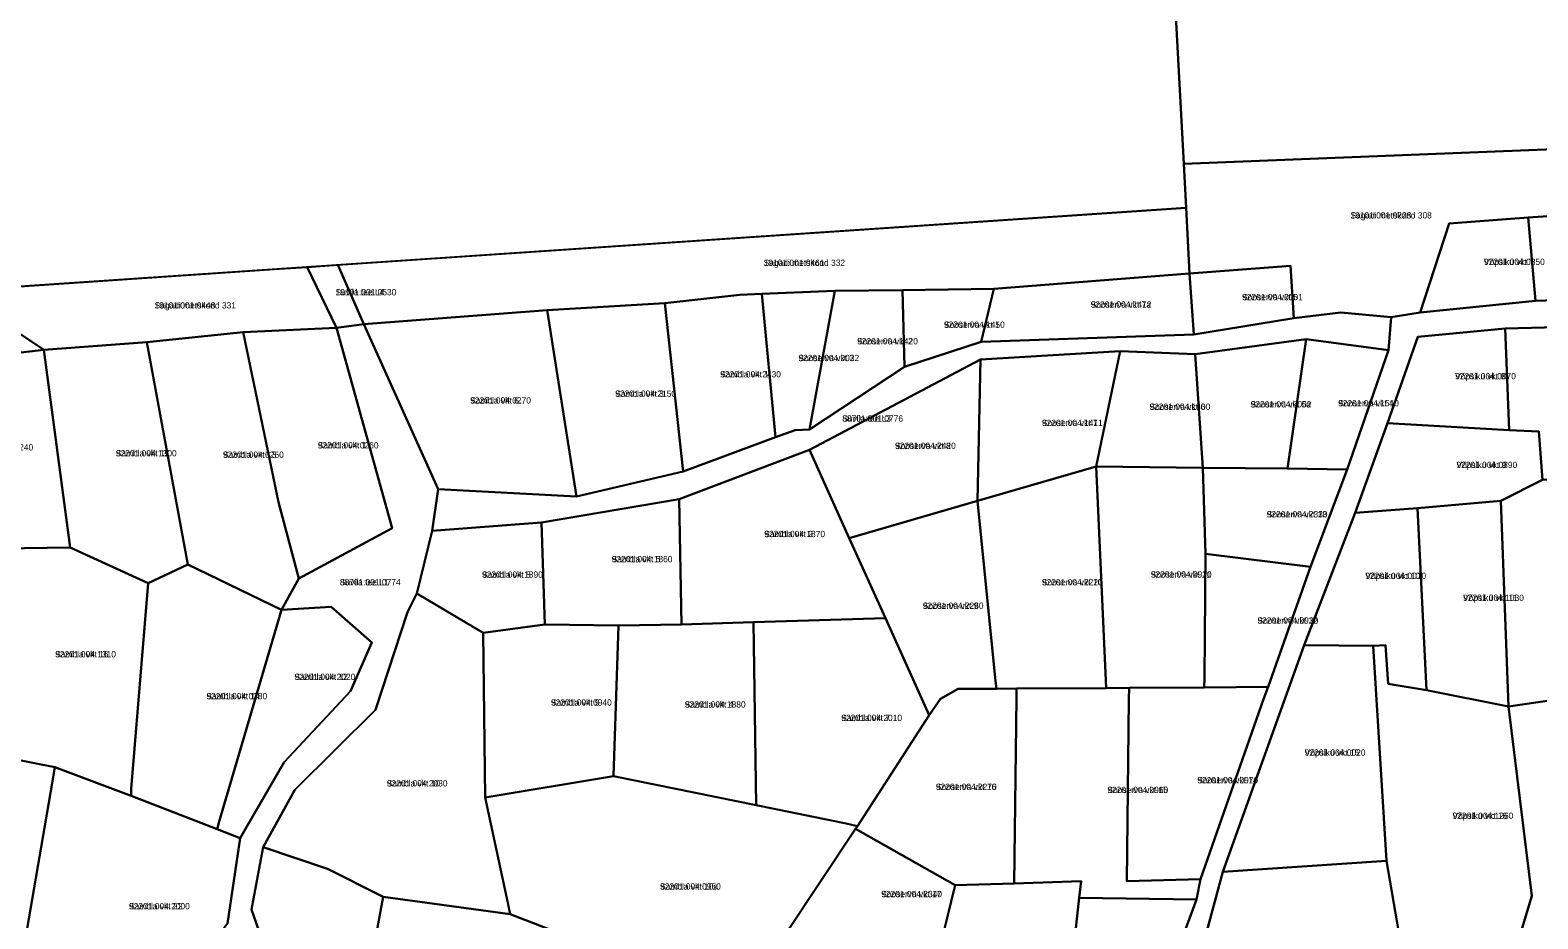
# Model space of a CAD drawing. Extents: x 601493 to 643081, y 6584980 to 6634019.
# Drawn here: x 609641.7 to 610001.3, y 6605459.3 to 6605671.2 of the extents above; entities that cross this region are included whole.
import ezdxf

# ---------------------------------------------------------------- set-up
doc = ezdxf.new("R2010")
doc.units = 0
for name, color, linetype in [('L_AADRESS', 7, 'Continuous'), ('PIIR', 7, 'Continuous'), ('TUNNUS', 7, 'Continuous')]:
    doc.layers.add(name, color=color, linetype=linetype)

msp = doc.modelspace()

# ---------------------------------------------------------------- linework, layer by layer
at = {"layer": 'PIIR'}
for points in [[(609908.54, 6605793.58), (609916.86, 6605639.32), (609917.44, 6605628.88), (609623.91, 6605609.09), (609512.83, 6605683.31)], [(609623.91, 6605609.09), (609645.03, 6605594.98), (609612.12, 6605591.18)], [(609898.91, 6605406.97), (609919.91, 6605463.95), (609920.89, 6605468.82), (609935.93, 6605511.68), (609936.98, 6605514.62), (609947.14, 6605543.25), (609955.84, 6605566.48), (609965.73, 6605594.92), (609966.33, 6605602.77), (609973.23, 6605603.88), (610000.76, 6605606.7), (610020.02, 6605607.29)], [(609688.83, 6605458.19), (609691.83, 6605478.59), (609693.08, 6605480.76), (609702.35, 6605496.71), (609718.16, 6605513.63), (609723.25, 6605525.24), (609713.54, 6605533.71), (609701.71, 6605533.02), (609705.85, 6605540.51), (609728.11, 6605552.51), (609714.83, 6605600.26), (609721.36, 6605601.15), (609739.05, 6605561.76), (609737.59, 6605551.83), (609733.95, 6605536.92), (609731.77, 6605532.43), (609724.11, 6605509.16), (609704.85, 6605490.08), (609697.35, 6605476.41), (609696.76, 6605473.45), (609694.51, 6605461.52), (609703.63, 6605435.58)], [(610018.55, 6605600.75), (609993.56, 6605600.07), (609972.71, 6605598.08), (609965.47, 6605577.51), (609957.77, 6605556.1), (609945.62, 6605524.56), (609926.24, 6605470.57), (609921.27, 6605452.23)], [(609625.52, 6605499.87), (609642.36, 6605496.51), (609647.66, 6605495.52), (609647, 6605491.64), (609638.8, 6605444.05)]]:
    msp.add_lwpolyline(points, dxfattribs=at)
for points in [[(610234, 6605735.88), (610224.92, 6605718.63), (610200.13, 6605689.04), (610179.93, 6605671.33), (610152.8, 6605650.08), (610007.23, 6605642.89), (609916.86, 6605639.32), (609908.54, 6605793.58), (609940.79, 6605777.71), (609965.38, 6605768.93), (609991.64, 6605761.28), (610037.32, 6605756.23), (610195.26, 6605740.09)], [(609916.86, 6605639.32), (610007.23, 6605642.89), (610152.8, 6605650.08), (610130.89, 6605636.35), (610107.22, 6605626.17), (610086.79, 6605623.63), (610075.1, 6605621.75), (610068.15, 6605618.37), (610067.52, 6605627.27), (610066.53, 6605637.45), (610046.56, 6605635), (610019.11, 6605631.81), (610019.32, 6605627.9), (609999.03, 6605626.57), (609980.21, 6605625.15), (609973.23, 6605603.88), (609966.33, 6605602.77), (609954.34, 6605603.92), (609943.14, 6605602.56), (609942.31, 6605615.03), (609918.27, 6605613.17), (609917.44, 6605628.88)], [(609715.12, 6605615.24), (609917.44, 6605628.88), (609918.27, 6605613.17), (609871.62, 6605609.56), (609849.79, 6605609.26), (609833.66, 6605609.04), (609816.28, 6605608.34), (609810.99, 6605608.08), (609793.09, 6605606.13), (609765.06, 6605604.43), (609721.36, 6605601.15)], [(610020.02, 6605607.29), (610000.76, 6605606.7), (609999.03, 6605626.57), (610019.32, 6605627.9)], [(609973.23, 6605603.88), (609980.21, 6605625.15), (609999.03, 6605626.57), (610000.76, 6605606.7)], [(609714.83, 6605600.26), (609692.55, 6605599.25), (609669.6, 6605596.85), (609645.03, 6605594.98), (609623.91, 6605609.09), (609701.09, 6605614.29), (609707.8, 6605614.74)], [(609707.8, 6605614.74), (609715.12, 6605615.24), (609721.36, 6605601.15), (609714.83, 6605600.26)], [(609868.53, 6605596.94), (609871.62, 6605609.56), (609918.27, 6605613.17), (609919.29, 6605598.62)], [(609919.29, 6605598.62), (609918.27, 6605613.17), (609942.31, 6605615.03), (609943.14, 6605602.56)], [(609816.28, 6605608.34), (609833.66, 6605609.04), (609827.65, 6605576.01), (609824.18, 6605575.88), (609819.51, 6605574.17)], [(609850.3, 6605590.94), (609827.65, 6605576.01), (609833.66, 6605609.04), (609849.79, 6605609.26)], [(609850.3, 6605590.94), (609849.79, 6605609.26), (609871.62, 6605609.56), (609868.53, 6605596.94)], [(609765.06, 6605604.43), (609793.09, 6605606.13), (609797.5, 6605566.02), (609772.01, 6605559.99)], [(609793.09, 6605606.13), (609810.99, 6605608.08), (609816.28, 6605608.34), (609819.51, 6605574.17), (609797.5, 6605566.02)], [(609739.05, 6605561.76), (609721.36, 6605601.15), (609765.06, 6605604.43), (609772.01, 6605559.99)], [(609739.05, 6605561.76), (609772.01, 6605559.99), (609797.5, 6605566.02), (609819.51, 6605574.17), (609824.18, 6605575.88), (609827.65, 6605576.01), (609850.3, 6605590.94), (609868.53, 6605596.94), (609919.29, 6605598.62), (609943.14, 6605602.56), (609954.34, 6605603.92), (609966.33, 6605602.77), (609965.73, 6605594.92), (609946.09, 6605597.51), (609919.57, 6605594), (609901.75, 6605594.65), (609868.4, 6605592.66), (609827.62, 6605571.14), (609796.53, 6605559.41), (609763.73, 6605553.81), (609737.59, 6605551.83)], [(609705.85, 6605540.51), (609701.71, 6605533.02), (609679.33, 6605543.79), (609669.6, 6605596.85), (609692.55, 6605599.25), (609700.96, 6605558.68)], [(609700.96, 6605558.68), (609692.55, 6605599.25), (609714.83, 6605600.26), (609728.11, 6605552.51), (609705.85, 6605540.51)], [(609965.47, 6605577.51), (609972.71, 6605598.08), (609993.56, 6605600.07), (609994.53, 6605575.84)], [(610001.59, 6605575.53), (609994.53, 6605575.84), (609993.56, 6605600.07), (610018.55, 6605600.75), (610018.06, 6605564.34), (610007.71, 6605564.11), (610002.42, 6605564)], [(609645.03, 6605594.98), (609651.31, 6605547.9), (609634.89, 6605547.6), (609604.6, 6605553.65), (609612.12, 6605591.18)], [(609651.31, 6605547.9), (609645.03, 6605594.98), (609669.6, 6605596.85), (609679.33, 6605543.79), (609669.87, 6605539.37)], [(609867.71, 6605558.98), (609868.4, 6605592.66), (609901.75, 6605594.65), (609896, 6605567.15)], [(609896, 6605567.15), (609901.75, 6605594.65), (609919.57, 6605594), (609921.43, 6605566.83)], [(609941.65, 6605566.7), (609921.43, 6605566.83), (609919.57, 6605594), (609946.09, 6605597.51)], [(609941.65, 6605566.7), (609946.09, 6605597.51), (609965.73, 6605594.92), (609955.84, 6605566.48)], [(609827.62, 6605571.14), (609868.4, 6605592.66), (609867.71, 6605558.98), (609837.07, 6605550.09)], [(609957.77, 6605556.1), (609965.47, 6605577.51), (609994.53, 6605575.84), (610001.59, 6605575.53), (610002.42, 6605564), (609992.54, 6605558.98), (609972.65, 6605557.24)], [(609797.12, 6605529.53), (609796.53, 6605559.41), (609827.62, 6605571.14), (609837.07, 6605550.09), (609845.72, 6605531.03), (609814.23, 6605530.09)], [(609872.19, 6605514.19), (609871.93, 6605516.78), (609867.71, 6605558.98), (609896, 6605567.15), (609898.32, 6605516.16), (609898.4, 6605514.35), (609876.98, 6605514.22)], [(609898.4, 6605514.35), (609898.32, 6605516.16), (609896, 6605567.15), (609921.43, 6605566.83), (609922.05, 6605546.36), (609921.79, 6605516.8), (609921.77, 6605514.49), (609903.83, 6605514.37)], [(609921.43, 6605566.83), (609941.65, 6605566.7), (609955.84, 6605566.48), (609947.14, 6605543.25), (609922.05, 6605546.36)], [(609992.54, 6605558.98), (610002.42, 6605564), (610007.71, 6605564.11), (610008.11, 6605554.01), (610008.7, 6605545.64), (610011.74, 6605512.52), (609994.37, 6605509.95)], [(609763.73, 6605553.81), (609796.53, 6605559.41), (609797.12, 6605529.53), (609782.1, 6605529.28), (609764.51, 6605529.52)], [(609845.72, 6605531.03), (609837.07, 6605550.09), (609867.71, 6605558.98), (609871.93, 6605516.78), (609872.19, 6605514.19), (609863.1, 6605514.13), (609858.9, 6605511.75), (609856.15, 6605507.91), (609855.11, 6605510.23)], [(609972.65, 6605557.24), (609992.54, 6605558.98), (609994.37, 6605509.95), (609974.78, 6605513.81)], [(609957.77, 6605556.1), (609972.65, 6605557.24), (609974.78, 6605513.81), (609965.63, 6605515.37), (609965.03, 6605524.54), (609962.05, 6605524.42), (609945.62, 6605524.56)], [(609733.95, 6605536.92), (609737.59, 6605551.83), (609763.73, 6605553.81), (609764.51, 6605529.52), (609749.82, 6605527.49)], [(609625.52, 6605499.87), (609625.9, 6605501.82), (609634.89, 6605547.6), (609651.31, 6605547.9), (609669.87, 6605539.37), (609665.86, 6605490.34), (609665.83, 6605488.63), (609647.66, 6605495.52), (609642.36, 6605496.51)], [(609921.79, 6605516.8), (609922.05, 6605546.36), (609947.14, 6605543.25), (609936.98, 6605514.62), (609921.77, 6605514.49)], [(609665.86, 6605490.34), (609669.87, 6605539.37), (609679.33, 6605543.79), (609701.71, 6605533.02), (609686.83, 6605482.53), (609686.36, 6605480.71), (609665.83, 6605488.63)], [(609712.66, 6605471.26), (609697.35, 6605476.41), (609704.85, 6605490.08), (609724.11, 6605509.16), (609731.77, 6605532.43), (609733.95, 6605536.92), (609749.82, 6605527.49), (609750.27, 6605488.22), (609755.65, 6605463.17), (609756.22, 6605460.46), (609725.96, 6605464.6)], [(609693.08, 6605480.76), (609691.83, 6605478.59), (609686.36, 6605480.71), (609686.83, 6605482.53), (609701.71, 6605533.02), (609713.54, 6605533.71), (609723.25, 6605525.24), (609718.16, 6605513.63), (609702.35, 6605496.71)], [(609782.1, 6605529.28), (609797.12, 6605529.53), (609814.23, 6605530.09), (609814.9, 6605486.39), (609780.85, 6605493.31)], [(609814.23, 6605530.09), (609845.72, 6605531.03), (609855.11, 6605510.23), (609856.15, 6605507.91), (609839.04, 6605481.46), (609836.33, 6605482.03), (609814.9, 6605486.39)], [(609780.85, 6605493.31), (609750.27, 6605488.22), (609749.82, 6605527.49), (609764.51, 6605529.52), (609782.1, 6605529.28)], [(609962.05, 6605524.42), (609965.23, 6605473.18), (609926.24, 6605470.57), (609945.62, 6605524.56)], [(609965.23, 6605473.18), (609962.05, 6605524.42), (609965.03, 6605524.54), (609965.63, 6605515.37), (609974.78, 6605513.81), (609994.37, 6605509.95), (609999.94, 6605464.84), (609995.96, 6605451.54), (609968.27, 6605455.6)], [(610058.99, 6605507.43), (610057.58, 6605500.17), (610049.03, 6605459.29), (610021.37, 6605455.21), (609995.96, 6605451.54), (609999.94, 6605464.84), (609994.37, 6605509.95), (610011.74, 6605512.52), (610021.25, 6605513.93), (610037.31, 6605516.37), (610061.39, 6605519.77)], [(609838.55, 6605480.77), (609839.04, 6605481.46), (609856.15, 6605507.91), (609858.9, 6605511.75), (609863.1, 6605514.13), (609872.19, 6605514.19), (609876.98, 6605514.22), (609876.96, 6605511.95), (609876.45, 6605467.78), (609862.37, 6605467.36)], [(609876.96, 6605511.95), (609876.98, 6605514.22), (609898.4, 6605514.35), (609903.83, 6605514.37), (609903.79, 6605511.61), (609903.27, 6605468.31), (609920.89, 6605468.82), (609919.91, 6605463.95), (609891.96, 6605464.36), (609892.42, 6605468.27), (609876.45, 6605467.78)], [(609903.79, 6605511.61), (609903.83, 6605514.37), (609921.77, 6605514.49), (609936.98, 6605514.62), (609935.93, 6605511.68), (609920.89, 6605468.82), (609903.27, 6605468.31)], [(609638.8, 6605444.05), (609647, 6605491.64), (609647.66, 6605495.52), (609665.83, 6605488.63), (609686.36, 6605480.71), (609691.83, 6605478.59), (609688.83, 6605458.19), (609669.22, 6605432), (609663.92, 6605435.17)], [(609755.65, 6605463.17), (609750.27, 6605488.22), (609780.85, 6605493.31), (609814.9, 6605486.39), (609836.33, 6605482.03), (609839.04, 6605481.46), (609838.55, 6605480.77), (609821.9, 6605455.66), (609811.03, 6605439.3), (609756.22, 6605460.46)], [(609821.9, 6605455.66), (609838.55, 6605480.77), (609862.37, 6605467.36), (609857.67, 6605448.22), (609823.76, 6605455.28)], [(609694.51, 6605461.52), (609696.76, 6605473.45), (609697.35, 6605476.41), (609712.66, 6605471.26), (609725.96, 6605464.6), (609725.29, 6605461.16), (609720.71, 6605436.15), (609703.63, 6605435.58)], [(609926.24, 6605470.57), (609965.23, 6605473.18), (609968.27, 6605455.6), (609965.91, 6605440.05), (609948.27, 6605436.8), (609921.27, 6605452.23)], [(609857.67, 6605448.22), (609862.37, 6605467.36), (609876.45, 6605467.78), (609892.42, 6605468.27), (609891.96, 6605464.36), (609889.4, 6605441.26)], [(609732.05, 6605432.18), (609707.15, 6605426.83), (609703.63, 6605435.58), (609720.71, 6605436.15), (609725.29, 6605461.16), (609725.96, 6605464.6), (609756.22, 6605460.46), (609811.03, 6605439.3), (609810.19, 6605436.99), (609790.11, 6605406.91), (609786.89, 6605407.92), (609759.99, 6605416.34)], [(609885.87, 6605411.37), (609886.02, 6605412.57), (609889.4, 6605441.26), (609891.96, 6605464.36), (609919.91, 6605463.95), (609898.91, 6605406.97)]]:
    msp.add_lwpolyline(points, close=True, dxfattribs=at)

# ---------------------------------------------------------------- texts
at = {"layer": 'L_AADRESS'}
for s, p in [('Sagadi metskond 308', (609956.65, 6605626.32)), ('Sagadi metskond 332', (609816.7, 6605615.01)), ('Võpsiku vkt 7', (609988.49, 6605615.23)), ('Suvila tee L4', (609714.58, 6605607.99)), ('Sagadi metskond 331', (609671.42, 6605604.86)), ('Sooserva vkt 7a', (609894.68, 6605605.06)), ('Sooserva vkt 5', (609930.79, 6605606.83)), ('Sooserva vkt 1', (609859.69, 6605600.25)), ('Sooserva vkt 2', (609838.97, 6605596.29)), ('Sooserva vkt 3', (609824.97, 6605592.3)), ('Sambla vkt 1', (609806.3, 6605588.42)), ('Võpsiku vkt 8', (609981.6, 6605587.96)), ('Sambla vkt 6', (609746.68, 6605582.2)), ('Sambla vkt 3', (609781.28, 6605583.8)), ('Sooserva vkt 6', (609908.71, 6605580.69)), ('Sooserva vkt 5a', (609932.83, 6605581.26)), ('Sooserva vkt 4', (609953.69, 6605581.51)), ('Suvila tee L3', (609835.43, 6605577.88)), ('Sooserva vkt 7', (609883.05, 6605576.82)), ('Sambla vkt 11', (609710.33, 6605571.49)), ('Sooserva vkt 8', (609848.01, 6605571.38)), ('Sambla vkt 15', (609662.18, 6605569.59)), ('Sambla vkt 13', (609687.73, 6605569.25)), ('Võpsiku vkt 9', (609981.92, 6605566.81)), ('Sooserva vkt 13', (609936.67, 6605555.04)), ('Sambla vkt 2', (609816.83, 6605550.34)), ('Sambla vkt 5', (609780.43, 6605544.35)), ('Sambla vkt 8', (609749.51, 6605540.65)), ('Sooserva vkt 11', (609909.02, 6605540.7)), ('Võpsiku vkt 10', (609960.2, 6605540.36)), ('Suvila tee L1', (609715.6, 6605538.84)), ('Sooserva vkt 10', (609883.05, 6605538.83)), ('Sooserva vkt 9', (609854.63, 6605533.24)), ('Võpsiku vkt 11', (609983.51, 6605535.14)), ('Sooserva vkt 12', (609934.46, 6605529.71)), ('Sambla vkt 16', (609647.7, 6605521.67)), ('Sambla vkt 12', (609704.8, 6605516.27)), ('Sambla vkt 14', (609683.77, 6605511.68)), ('Sambla vkt 9', (609765.96, 6605510.17)), ('Sambla vkt 4', (609797.88, 6605509.7)), ('Sambla vkt 7', (609835.19, 6605506.49)), ('Võpsiku vkt 15', (609945.73, 6605498.22)), ('Sambla vkt 10', (609726.79, 6605490.89)), ('Sooserva vkt 16', (609857.76, 6605490.06)), ('Sooserva vkt 15', (609898.67, 6605489.31)), ('Sooserva vkt 14', (609920.12, 6605491.64)), ('Võpsiku vkt 16', (609980.99, 6605483.16)), ('Sambla vkt 10a', (609791.97, 6605466.3)), ('Sooserva vkt 17', (609844.71, 6605464.49)), ('Sambla vkt 22', (609665.31, 6605461.58))]:
    msp.add_text(s, height=1.5, dxfattribs=at).set_placement(p)
at = {"layer": 'TUNNUS'}
for s, p in [('19101:001:0228', (609956.65, 6605626.32)), ('19101:001:0461', (609816.7, 6605615.01)), ('92201:004:0850', (609988.49, 6605615.23)), ('19101:001:0530', (609714.58, 6605607.99)), ('19101:001:0448', (609671.42, 6605604.86)), ('92201:004:1412', (609894.68, 6605605.06)), ('92201:004:0001', (609930.79, 6605606.83)), ('92201:004:1450', (609859.69, 6605600.25)), ('92201:004:1420', (609838.97, 6605596.29)), ('92201:004:0022', (609824.97, 6605592.3)), ('92201:004:2430', (609806.3, 6605588.42)), ('92201:004:0870', (609981.6, 6605587.96)), ('92201:004:0270', (609746.68, 6605582.2)), ('92201:004:2150', (609781.28, 6605583.8)), ('92201:004:1400', (609908.71, 6605580.69)), ('92201:004:0002', (609932.83, 6605581.26)), ('92201:004:1510', (609953.69, 6605581.51)), ('88701:001:0776', (609835.43, 6605577.88)), ('92201:004:1411', (609883.05, 6605576.82)), ('92201:004:0260', (609710.33, 6605571.49)), ('92201:004:2420', (609848.01, 6605571.38)), ('92201:004:0240', (609627.96, 6605571)), ('92201:004:1300', (609662.18, 6605569.59)), ('92201:004:0250', (609687.73, 6605569.25)), ('92201:004:0890', (609981.92, 6605566.81)), ('92201:004:2330', (609936.67, 6605555.04)), ('92201:004:1870', (609816.83, 6605550.34)), ('92201:004:1860', (609780.43, 6605544.35)), ('92201:004:1890', (609749.51, 6605540.65)), ('92201:004:0920', (609909.02, 6605540.7)), ('92201:004:0010', (609960.2, 6605540.36)), ('88701:001:0774', (609715.6, 6605538.84)), ('92201:004:2220', (609883.05, 6605538.83)), ('92201:004:2260', (609854.63, 6605533.24)), ('92201:004:1030', (609983.51, 6605535.14)), ('92201:004:0930', (609934.46, 6605529.71)), ('92201:004:1310', (609647.7, 6605521.67)), ('92201:004:2020', (609704.8, 6605516.27)), ('92201:004:0280', (609683.77, 6605511.68)), ('92201:004:0940', (609765.96, 6605510.17)), ('92201:004:1880', (609797.88, 6605509.7)), ('92201:004:2010', (609835.19, 6605506.49)), ('92201:004:0020', (609945.73, 6605498.22)), ('92201:004:2030', (609726.79, 6605490.89)), ('92201:004:2270', (609857.76, 6605490.06)), ('92201:004:0960', (609898.67, 6605489.31)), ('92201:004:0970', (609920.12, 6605491.64)), ('92201:004:1260', (609980.99, 6605483.16)), ('92201:004:0950', (609791.97, 6605466.3)), ('92201:004:2340', (609844.71, 6605464.49)), ('92201:004:2000', (609665.31, 6605461.58))]:
    msp.add_text(s, height=1.5, dxfattribs=at).set_placement(p)

doc.saveas('drawing.dxf')
